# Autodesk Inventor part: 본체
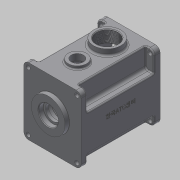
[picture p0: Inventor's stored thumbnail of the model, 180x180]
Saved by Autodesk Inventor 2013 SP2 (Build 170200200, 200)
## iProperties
Created: 2016-02
Part Number: 본체
Material: 일반
Document SubType Name: Modeling
Designer: mduedu
Density: 1 g/cm^3
Author: mduedu
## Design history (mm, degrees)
sketch "스케치1"
  geometry: L1 (-47, -47)-(47, -47); L2 (47, -47)-(47, 63); L3 (47, 63)-(-47, 63); L4 (-47, 63)-(-47, -47); 2 further points
  constraints: 8 end point, 2 parallel, 1 horizontal, 1 midpoint, 1 perpendicular, 1 vertical alignment
  dimensions: "d0" = 94 distance of L2.end L3.end; "d155" = 110 distance of L1.end L2.end; "d156" = 47 distance from line of L1 point (0, 0)
extrude "돌출1" new body sketch "스케치1" distance "d2" = 130; taper "d3" = 0 deg
sketch "스케치3"
  geometry: C1 r 40 at (0, 0); 1 further point
  constraints: 1 centre point, 1 coincident
  dimensions: "d9" = 80 diameter of C1
extrude "돌출3" cut sketch "스케치3" distance "d11" = 121; taper "d12" = 0 deg
sketch "스케치4"
  geometry: C1 r 21 at (0, 11); 1 further point
  constraints: 1 centre point, 1 vertical alignment
  dimensions: "d13" = 21 radius of C1; "d15" = 11 distance of point (0, 0) C1.centre
extrude "돌출4" join sketch "스케치4" distance "d16" = 7; taper "d17" = 0 deg
sketch "스케치5"
  geometry: C1 r 15 at (0, -20); 1 further point
  constraints: 1 centre point, 1 vertical alignment
  dimensions: "d18" = 15 radius of C1; "d20" = 20 distance of point (0, 0) C1.centre
extrude "돌출5" join sketch "스케치5" distance "d21" = 7; taper "d22" = 0 deg
sketch "스케치6"
  geometry: C1 r 28 at (0, 11); A1 r 21 centre (0, 11) between (8.978, -7.984) and (-8.978, -7.984) reference; 1 further point
  constraints: 1 centre point, 1 coincident
  dimensions: "d23" = 56 diameter of C1
extrude "돌출6" join sketch "스케치6" distance "d25" = 7; taper "d26" = -3 deg
hole "구멍1" diameter "d29" = 35; stored, may be unused: countersink angle "d33" = 90 deg, drill point angle "d35" = 0 deg; dims "d27" = 10, "d28" = 10, "d30" = 6, "d31" = 4, "d32" = 2, "d34" = 10
hole "구멍2" diameter "d38" = 22; stored, may be unused: countersink angle "d42" = 90 deg, drill point angle "d44" = 0 deg; dims "d36" = 10, "d37" = 10, "d39" = 6, "d40" = 4, "d41" = 2, "d43" = 7
hole "구멍3" diameter "d47" = 19; stored, may be unused: countersink angle "d51" = 90 deg, drill point angle "d53" = 0 deg; dims "d45" = 10, "d46" = 10, "d48" = 6, "d49" = 4, "d50" = 2, "d52" = 1
hole "구멍4" diameter "d56" = 32; stored, may be unused: countersink angle "d60" = 90 deg, drill point angle "d62" = 0 deg; dims "d54" = 10, "d55" = 10, "d57" = 6, "d58" = 4, "d59" = 2, "d61" = 8
hole "구멍5" diameter "d65" = 25; stored, may be unused: countersink angle "d69" = 90 deg, drill point angle "d71" = 0 deg; dims "d63" = 10, "d64" = 10, "d66" = 6, "d67" = 4, "d68" = 2, "d70" = 8
fillet "모깎기2" dims "d73" = 0.3
fillet "모깎기3" dims "d74" = 2
chamfer "모따기1" distance "d75" = 1; stored, may be unused: second distance "d76" = 2, angle "d77" = 45 deg
fillet "모깎기4" dims "d78" = 3
sketch "스케치16"
  geometry: L1 (-23, 32.726)-(23, 32.726); L2 (23, 32.726)-(23, 53); L3 (23, 53)-(-23, 53); L4 (-23, 53)-(-23, 32.726); L5 (-47, 63)-(47, 63) reference; 3 further points
  constraints: 8 end point, 2 parallel, 1 horizontal, 1 midpoint, 1 perpendicular, 1 vertical alignment, 2 other
  dimensions: "d160" = 46 distance of L2.end L3.end; "d163" = 10 distance between parallel lines of L3 L5
extrude "돌출15" cut sketch "스케치16" stored distance "d164" = 10; taper "d165" = 0 deg
fillet "모깎기5" dims "d79" = 2
fillet "모깎기15" dims "d166" = 5
sketch "스케치7"
  geometry: L1 (-23, 48)-(-23, 35.228) reference; L2 (23, 35.228)-(23, 48) reference; L3 (18, 53)-(-18, 53) reference; L4 (47, 63)-(47, -47) reference; L5 (47, -47)-(-47, -47) reference; L6 (-47, -47)-(-47, 63) reference; L7 (-47, 63)-(47, 63) reference; L8 (-26, 48)-(-26, 35.228); L9 (26, 35.228)-(26, 48); L10 (18, 56)-(-18, 56); C1 r 43 at (0, 0); A1 r 5 centre (-18, 48) between (-18, 53) and (-23, 48) reference; A2 r 5 centre (-28, 35.228) between (-24.889, 31.314) and (-23, 35.228) reference; A3 r 40 centre (0, 0) between (-24.889, 31.314) and (24.889, 31.314) reference; A4 r 5 centre (28, 35.228) between (23, 35.228) and (24.889, 31.314) reference; A5 r 5 centre (18, 48) between (23, 48) and (18, 53) reference; A6 r 8 centre (-18, 48) between (-18, 56) and (-26, 48); A7 r 2 centre (-28, 35.228) between (-26.756, 33.662) and (-26, 35.228); A8 r 43 centre (0, 0) between (-26.756, 33.662) and (26.756, 33.662); A9 r 2 centre (28, 35.228) between (26, 35.228) and (26.756, 33.662); A10 r 8 centre (18, 48) between (26, 48) and (18, 56); 1 further point
  constraints: 10 point on circle, 6 centre point, 6 end point, 1 coincident, 7 other
  dimensions: "d80" = 86 diameter of C1; "d167" = 3 distance between parallel lines of L3 L10
extrude "돌출7" cut sketch "스케치7" distance "d83" = 9; taper "d84" = 0 deg
sketch "스케치8" dims "d168" = 36
  geometry: L1 (-36, 4)-(-39.799, 4); L2 (-36, -4)-(-39.799, -4); A1 r 4 centre (-36, 0) between (-36, 4) and (-36, -4); A2 r 40 centre (0, 0) between (-24.889, 31.314) and (24.889, 31.314) reference; A3 r 40 centre (0, 0) between (-39.799, 4) and (-39.799, -4); 2 further points
  constraints: 5 point on circle, 4 end point, 2 centre point, 2 coincident, 2 horizontal alignment, 2 tangent, 1 horizontal, 1 parallel, 2 other
  dimensions: "d169" = 4 radius of A1
extrude "돌출9" join sketch "스케치8" stored distance "d89" = 9; taper "d90" = 0 deg
fillet "모깎기6" dims "d91" = 3.5
node "작업 평면1"
sketch "스케치9"
  geometry: L1 (47, 63)-(33, 63); L2 (33, 63)-(33, 30); L3 (33, 30)-(47, 30); L4 (47, 30)-(47, 63); L5 (47, 63)-(-47, 63) reference; L6 (47, -47)-(47, 63) reference; A1 r 40 centre (0, 0) between (-39.148, -8.214) and (39.148, -8.214) reference; 1 further point
  constraints: 8 end point, 2 parallel, 1 coincident, 1 horizontal, 1 perpendicular
  dimensions: "d95" = 33 distance from line of L2 point (0, 0); "d96" = 30 distance from line of L3 point (0, 0)
extrude "돌출10" cut sketch "스케치9" distance "d97" = 110; taper "d98" = 0 deg
sketch "스케치11"
  geometry: L1 (-40, -40)-(40, -40); L2 (40, -40)-(40, 56); L3 (40, 56)-(-40, 56); L4 (-40, 56)-(-40, -40); L5 (-47, -47)-(47, -47) reference; L6 (47, 63)-(-47, 63) reference; L7 (-47, 63)-(-47, -47) reference; C1 r 3.5 at (-40, 56); C2 r 3.5 at (40, 56); C3 r 3.5 at (40, -40); C4 r 3.5 at (-40, -40); 1 further point
  constraints: 8 end point, 4 centre point, 4 coincident, 3 equal radius, 2 parallel, 1 horizontal, 1 perpendicular
  dimensions: "d109" = 80 distance of L2.end L3.end; "d112" = 7 diameter of C1; "d157" = 7 distance from line of L1.start L5; "d158" = 7 distance between parallel lines of L6 L3; "d159" = 7 distance from line of L7 L3.end
extrude "돌출12" cut sketch "스케치11" stored distance "d113" = 63; taper "d114" = 0 deg
fillet "모깎기7" dims "d115" = 8, "d187" = 8
fillet "모깎기8" dims "d116" = 5
fillet "모깎기11" dims "d119" = 2, "d188" = 2
fillet "모깎기12" dims "d120" = 2
fillet "모깎기13" dims "d121" = 2
sketch "스케치12"
  geometry: 3 further points
  constraints: 2 horizontal alignment
hole "구멍6" sketch "스케치12" at (36, 0), (-36, 0) diameter "d122" = 3.242; stored, may be unused: countersink angle "d126" = 90 deg, drill point angle "d128" = 120 deg; dims "d123" = 7, "d124" = 4, "d125" = 2, "d127" = 9
fillet "모깎기14" dims "d147" = 0.3
chamfer "모따기4" distance "d151" = 1; stored, may be unused: second distance "d152" = 2, angle "d153" = 45 deg
sketch "스케치20"
  geometry: L1 (74, -122)-(78, -122) reference; L2 (70, -12)-(70, -118) reference; L3 (78, -8)-(74, -8) reference; L4 (78, 0)-(78, -8) reference; L5 (78, 0)-(0, 0) reference; L6 (0, -8)-(0, 0) reference; L7 (4, -8)-(0, -8) reference; L8 (8, -118)-(8, -12) reference; L9 (0, -122)-(4, -122) reference; L10 (0, -130)-(0, -122) reference; L11 (78, -130)-(0, -130) reference; L12 (78, -122)-(78, -130) reference; L13 (39, 0)-(39, -130); C1 r 10 at (39, -89); A1 r 4 centre (74, -118) between (70, -118) and (74, -122) reference; A2 r 4 centre (74, -12) between (74, -8) and (70, -12) reference; A3 r 4 centre (4, -12) between (8, -12) and (4, -8) reference; A4 r 4 centre (4, -118) between (4, -122) and (8, -118) reference
  constraints: 2 end point, 1 centre point, 1 midpoint, 1 point on line
  dimensions: "d189" = 20 diameter of C1; "d190" = 41 distance from line of C1.centre L11
extrude "돌출19" cut sketch "스케치20" stored distance "d191" = 10; taper "d192" = 0 deg
sketch "스케치18"
  geometry: C1 r 15 at (39, -89); C2 r 10 at (39, -89) reference; 1 further point
  constraints: 1 centre point, 1 concentric
  dimensions: "d174" = 30 diameter of C1
extrude "돌출17" join sketch "스케치18" distance "d175" = 5; taper "d176" = 0 deg
fillet "모깎기16" dims "d177" = 2
sketch "스케치19"
  geometry: C1 r 10 at (18, 80) reference; C2 r 15 at (18, 80); 1 further point
  constraints: 1 centre point, 1 coincident
  dimensions: "d178" = 30 diameter of C2
extrude "돌출18" cut sketch "스케치19" distance "d181" = 5; taper "d182" = 0 deg
chamfer "모따기5" distance "d183" = 0.5; stored, may be unused: second distance "d184" = 2, angle "d185" = 45 deg
sketch "스케치21"
  geometry: L1 (-122, 7)-(-122, 0) reference; L2 (-12, 11)-(-118, 11) reference; L3 (-8, 0)-(-8, 7) reference; L4 (0, 0)-(-8, 0) reference; L5 (0, 0)-(0, 94) reference; L6 (-8, 94)-(0, 94) reference; L7 (-8, 71)-(-8, 94) reference; L8 (-118, 67)-(-12, 67) reference; L9 (-122, 94)-(-122, 71) reference; L10 (-130, 94)-(-122, 94) reference; L11 (-130, 0)-(-130, 94) reference; L12 (-122, 0)-(-130, 0) reference; L13 (-130, 47)-(0, 47); A1 r 4 centre (-118, 7) between (-118, 11) and (-122, 7) reference; A2 r 4 centre (-12, 7) between (-8, 7) and (-12, 11) reference; A3 r 4 centre (-12, 71) between (-12, 67) and (-8, 71) reference; A4 r 4 centre (-118, 71) between (-122, 71) and (-118, 67) reference; 3 further points
  constraints: 3 midpoint, 2 end point, 1 coincident, 1 other
feature "엠보싱2" sketch "스케치21" dims "d193" = 0.5, "d194" = 0
sketch "스케치22"
  geometry: L1 (74, -122)-(78, -122) reference; L2 (70, -12)-(70, -118) reference; L3 (78, -8)-(74, -8) reference; L4 (78, 0)-(78, -8) reference; L5 (78, 0)-(0, 0) reference; L6 (0, -8)-(0, 0) reference; L7 (4, -8)-(0, -8) reference; L8 (8, -118)-(8, -12) reference; L9 (0, -122)-(4, -122) reference; L10 (0, -130)-(0, -122) reference; L11 (78, -130)-(0, -130) reference; L12 (78, -122)-(78, -130) reference; L13 (39, -130)-(39, 0); C1 r 17 at (39, -89) reference; C2 r 22.5 at (39, -40); A1 r 4 centre (74, -118) between (70, -118) and (74, -122) reference; A2 r 4 centre (74, -12) between (74, -8) and (70, -12) reference; A3 r 4 centre (4, -12) between (8, -12) and (4, -8) reference; A4 r 4 centre (4, -118) between (4, -122) and (8, -118) reference
  constraints: 2 end point, 1 centre point, 1 midpoint, 1 parallel, 1 point on line
  dimensions: "d195" = 45 diameter of C2; "d197" = 40 distance from line of C2.centre L5
extrude "돌출20" join sketch "스케치22" distance "d198" = 10; taper "d199" = 0 deg
fillet "모깎기17" dims "d200" = 3
hole "구멍7" diameter "d203" = 35; stored, may be unused: countersink angle "d207" = 90 deg, drill point angle "d209" = 118 deg; dims "d204" = 6, "d205" = 4, "d206" = 2, "d208" = 8, "d213" = 10, "d214" = 10
feature "스레드1" dims "d215" = 10, "d216" = 0
chamfer "모따기6" distance "d210" = 1; stored, may be unused: second distance "d211" = 2, angle "d212" = 45 deg
node "솔리드1"
pattern_circular "원형 패턴1" dims angle "d93" = 360 deg
mirror "대칭1"
mirror "대칭2"
node "투영된 루프1"
node "투영된 루프2"
node "투영된 루프3"
node "절단 모서리 투영3"
